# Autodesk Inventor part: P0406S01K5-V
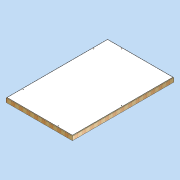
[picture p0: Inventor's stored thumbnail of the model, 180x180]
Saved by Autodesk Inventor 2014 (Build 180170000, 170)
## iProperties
Created: 2011-04
Part Number: P0406S01K5-V
Document SubType Name: Modeling
Designer: david.appleford
Density: 0.185545 g/cm^3
Description: 1w x 1.5w 01 Panel - 5 Locks
Mass: 30000 g
Surface Area: 45265.3 cm^2
Volume: 161686 cm^3
Cost Center: £108.00
Material: Generic
Appearance: Wood (Pine)
Justset: False
Title: 1w x 1.5w 01 Panel - 5 Locks
Author: david.appleford
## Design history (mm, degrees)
sketch "Sketch1"
  geometry: L1 (0, 0)-(1220, 0); L2 (1220, 0)-(1220, 1830); L3 (1220, 1830)-(0, 1830); L4 (0, 1830)-(0, 0); L5 (34, 1796)-(1186, 1796); L6 (1186, 1796)-(1186, 34); L7 (1186, 34)-(34, 34); L8 (34, 34)-(34, 1796)
  constraints: 16 end point, 4 parallel, 2 perpendicular, 1 horizontal, 3 other
  dimensions: "d0" = 1220 distance between parallel lines of L2 L4 (= w); "d1" = 1830 distance between parallel lines of L1 L3 (= 1.5 x w); "d2" = 34 distance between parallel lines of L5 L3 (= 0.5 x t)
extrude "Extrusion1" new body sketch "Sketch1" distance "d3" = 68 (= t); taper "d4" = 0 deg
sketch "Sketch2"
  geometry: L1 (1186, 1796)-(1186, 34) reference; L2 (34, 1796)-(1186, 1796) reference; L3 (34, 34)-(34, 1796) reference; L4 (1186, 34)-(34, 34) reference; L5 (1176, 1786)-(1176, 44); L6 (1176, 44)-(44, 44); L7 (44, 44)-(44, 1786); L8 (44, 1786)-(1176, 1786); 1 further point
  constraints: 8 end point, 3 other
  dimensions: "d5" = 10 distance between parallel lines of L8 L2
extrude "Extrusion2" join sketch "Sketch2" distance "d6" = 6 (= sw); taper "d7" = 0 deg
sketch "Sketch3"
  geometry: L1 (-44, 1786)-(-1176, 1786) reference; L2 (-1176, 1786)-(-1176, 44) reference; L3 (-44, 44)-(-44, 1786) reference; L4 (-1176, 44)-(-44, 44) reference; 1 further point
extrude "Extrusion3" join sketch "Sketch3" distance "d8" = 6 (= sw); taper "d9" = 0 deg
sketch "Sketch4"
  geometry: L1 (34, 1796)-(1186, 1796) reference; L2 (1186, 1796)-(1186, 34) reference; L3 (1186, 34)-(34, 34) reference; L4 (34, 34)-(34, 1796) reference; 6 further points
  constraints: 1 vertical alignment
  dimensions: "d10" = 28 distance from line of point (305, 1768) L1 (= k); "d12" = 28 distance from line of L3 point (915, 62) (= k); "d13" = 28 distance from line of point (62, 305) L4 (= k); "d14" = 305 horizontal distance of point (305, 1768) point (0, 0) (= 0.25 x w); "d15" = 610 horizontal distance of point (915, 62) point (305, 1768) (= 0.5 x w); "d16" = 305 vertical distance of point (62, 305) point (0, 0) (= 0.25 x w); "d17" = 1220 distance of point (62, 305) point (62, 1525) (= w); "d19" = 610 vertical distance of point (1158, 915) point (62, 305) (= 0.5 x w)
hole "Hole1" sketch "Sketch4" at (305, 1768), (62, 1525), (62, 305), (1158, 915), (915, 62) diameter "d22" = 12 (= hd); stored, may be unused: countersink angle "d26" = 90 deg, drill point angle "d28" = 118 deg; dims "d23" = 6, "d24" = 4, "d25" = 2, "d27" = 8
body "Solid1"
node "Projected Loop1"
other parameters: "w" = 1220 [user parameter; used in 7 equation terms], "t" = 68 [user parameter; used in 2 equation terms], "e" = 16 [user parameter], "sw" = 6 [user parameter; used in 2 equation terms], "sc" = 9 [user parameter], "sf" = 12 [user parameter], "k" = 28 [user parameter; used in 3 equation terms], "hd" = 12 [user parameter; used in 1 equation term]
